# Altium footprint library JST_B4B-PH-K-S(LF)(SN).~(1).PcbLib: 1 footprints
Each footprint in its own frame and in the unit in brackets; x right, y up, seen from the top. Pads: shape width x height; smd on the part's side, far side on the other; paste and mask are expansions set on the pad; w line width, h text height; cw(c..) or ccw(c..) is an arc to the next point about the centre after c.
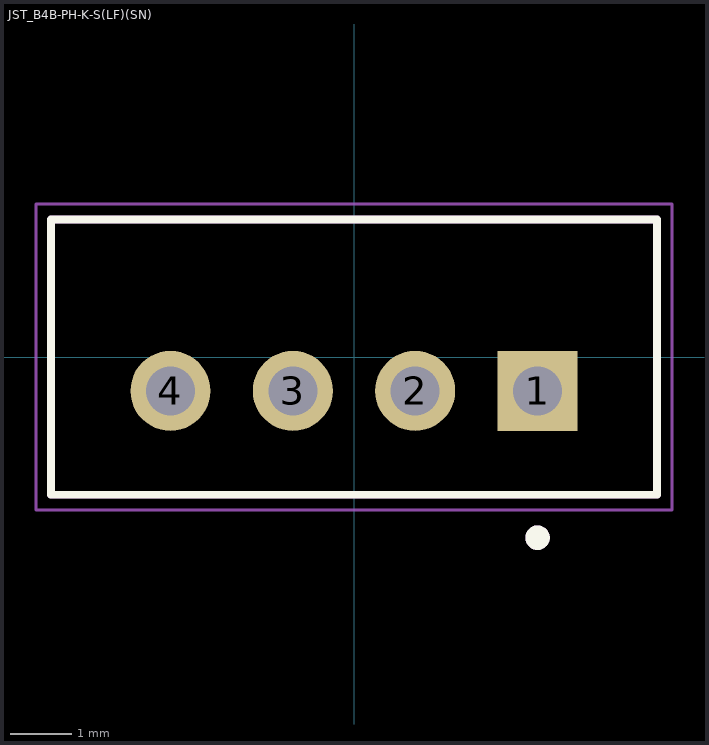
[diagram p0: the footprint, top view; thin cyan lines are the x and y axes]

## JST_B4B-PH-K-S(LF)(SN) [mm]
pads (4):
  rect 1.308x1.308 / inner round 1.308 / far side rect 1.308x1.308 hole 0.8: 1(3,-0.55)
  round 1.308 hole 0.8: 2(1,-0.55) 3(-1,-0.55) 4(-3,-0.55)
Top Overlay:
  circle w0.2: c3,-2.95 r0.1
  lines w0.127: -4.95,-2.25 -4.95,2.25 4.95,2.25 4.95,-2.25 -4.95,-2.25
Assembly Top:
  circle w0.2: c3,-2.95 r0.1
  lines w0.127: -4.95,-2.25 4.95,-2.25 4.95,2.25 -4.95,2.25 -4.95,-2.25
Courtyard Top:
  lines w0.05: -5.2,-2.5 5.2,-2.5 5.2,2.5 -5.2,2.5 -5.2,-2.5
3D body "step_temp.STEP": height 6, standoff -3.4, extent -4.95,-2.25 4.95,2.25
